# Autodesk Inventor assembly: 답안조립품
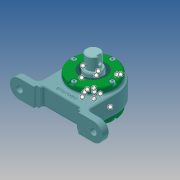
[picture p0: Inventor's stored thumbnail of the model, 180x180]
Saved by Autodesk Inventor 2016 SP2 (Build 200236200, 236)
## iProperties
Created: 2019-05
Part Number: 답안조립품
Document SubType Name: Assembly
Designer: EZ
Author: EZ
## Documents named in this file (13)
- Y:\490504V1004 윤중현\답안조립품.iam
- Y:\490504V1004 윤중현\개스킷.ipt
- Y:\490504V1004 윤중현\그리스니플 M6.ipt
- 그리스니플  M6.ipt
- Y:\490504V1004 윤중현\그리스니플개스킷.ipt
- Y:\490504V1004 윤중현\베어링너트.ipt
- Y:\490504V1004 윤중현\본체.ipt
- Y:\490504V1004 윤중현\볼트 M4.ipt
- Y:\490504V1004 윤중현\앵귤러 볼 베어링 7205.ipt
- Y:\490504V1004 윤중현\오일 실 28 40 5 B.ipt
- Y:\490504V1004 윤중현\축.ipt
- Y:\490504V1004 윤중현\칼라.ipt
- Y:\490504V1004 윤중현\커버.ipt
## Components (4 placed, 3 different names)
1. 개스킷:1
2. 그리스니플  M6:1
3. 그리스니플개스킷:1
4. 개스킷:2
